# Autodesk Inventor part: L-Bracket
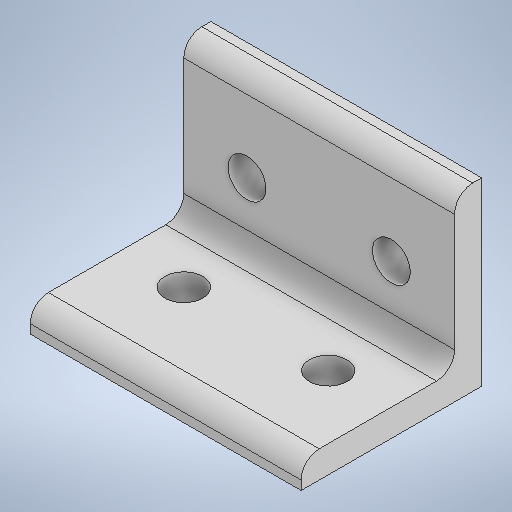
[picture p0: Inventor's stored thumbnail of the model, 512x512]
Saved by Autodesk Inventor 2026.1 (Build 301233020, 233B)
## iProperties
Created: 2026-11
Part Number: L-Bracket
Material: Generic
Document SubType Name: Modeling
Designer: hp
Density: 1 g/cm^3
Appearance: Default
Author: hp
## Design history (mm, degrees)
sketch "Sketch1"
  geometry: L1 (0, 0)-(30, 0); L2 (30, 0)-(30, 20); L3 (30, 20)-(0, 20); L4 (0, 20)-(0, 0); L5 (0, 3)-(30, 3); L6 (15, 20)-(15, 0); C1 r 2.1 at (7, 10); C2 r 2.1 at (23, 10); 1 further point
  constraints: 12 end point, 3 midpoint, 2 centre point, 2 parallel, 2 perpendicular, 2 point on line, 1 horizontal, 1 horizontal alignment, 1 symmetric about line, 1 other
  dimensions: "d0" = 30 distance of L3.end L2.end; "d1" = 20 distance of L1.end L2.end; "d2" = 3 distance between parallel lines of L1 L5; "d3" = 4.2 diameter of C1; "d4" = 7 distance from line of L4 C1.centre
extrude "Extrusion1" new body sketch "Sketch1" distance "d5" = 3 (= d2); taper "d6" = 0 deg
extrude "Extrusion2" join sketch "Sketch1" distance "d7" = 17; taper "d8" = 0 deg
sketch "Sketch3"
  geometry: L1 (0, -17)-(30, -17); L2 (30, -17)-(30, 3); L3 (30, 3)-(0, 3); L4 (0, 3)-(0, -17); L5 (0, -14)-(30, -14); L6 (15, 3)-(15, -17); C1 r 2.1 at (7, -7); C2 r 2.1 at (23, -7); 3 further points
  constraints: 12 end point, 3 midpoint, 2 centre point, 2 parallel, 2 perpendicular, 2 point on line, 1 coincident, 1 horizontal, 1 horizontal alignment, 1 symmetric about line, 1 other
  dimensions: "d16" = 30 distance of L3.end L2.end; "d17" = 20 distance of L1.end L2.end; "d18" = 3 distance between parallel lines of L1 L5; "d19" = 4.2 diameter of C1; "d20" = 7 distance from line of L4 C1.centre
extrude "Extrusion4" cut sketch "Sketch3" stored distance "d21" = 10; taper "d22" = 0 deg
fillet "Fillet1" dims "d23" = 2
body "Solid1"
